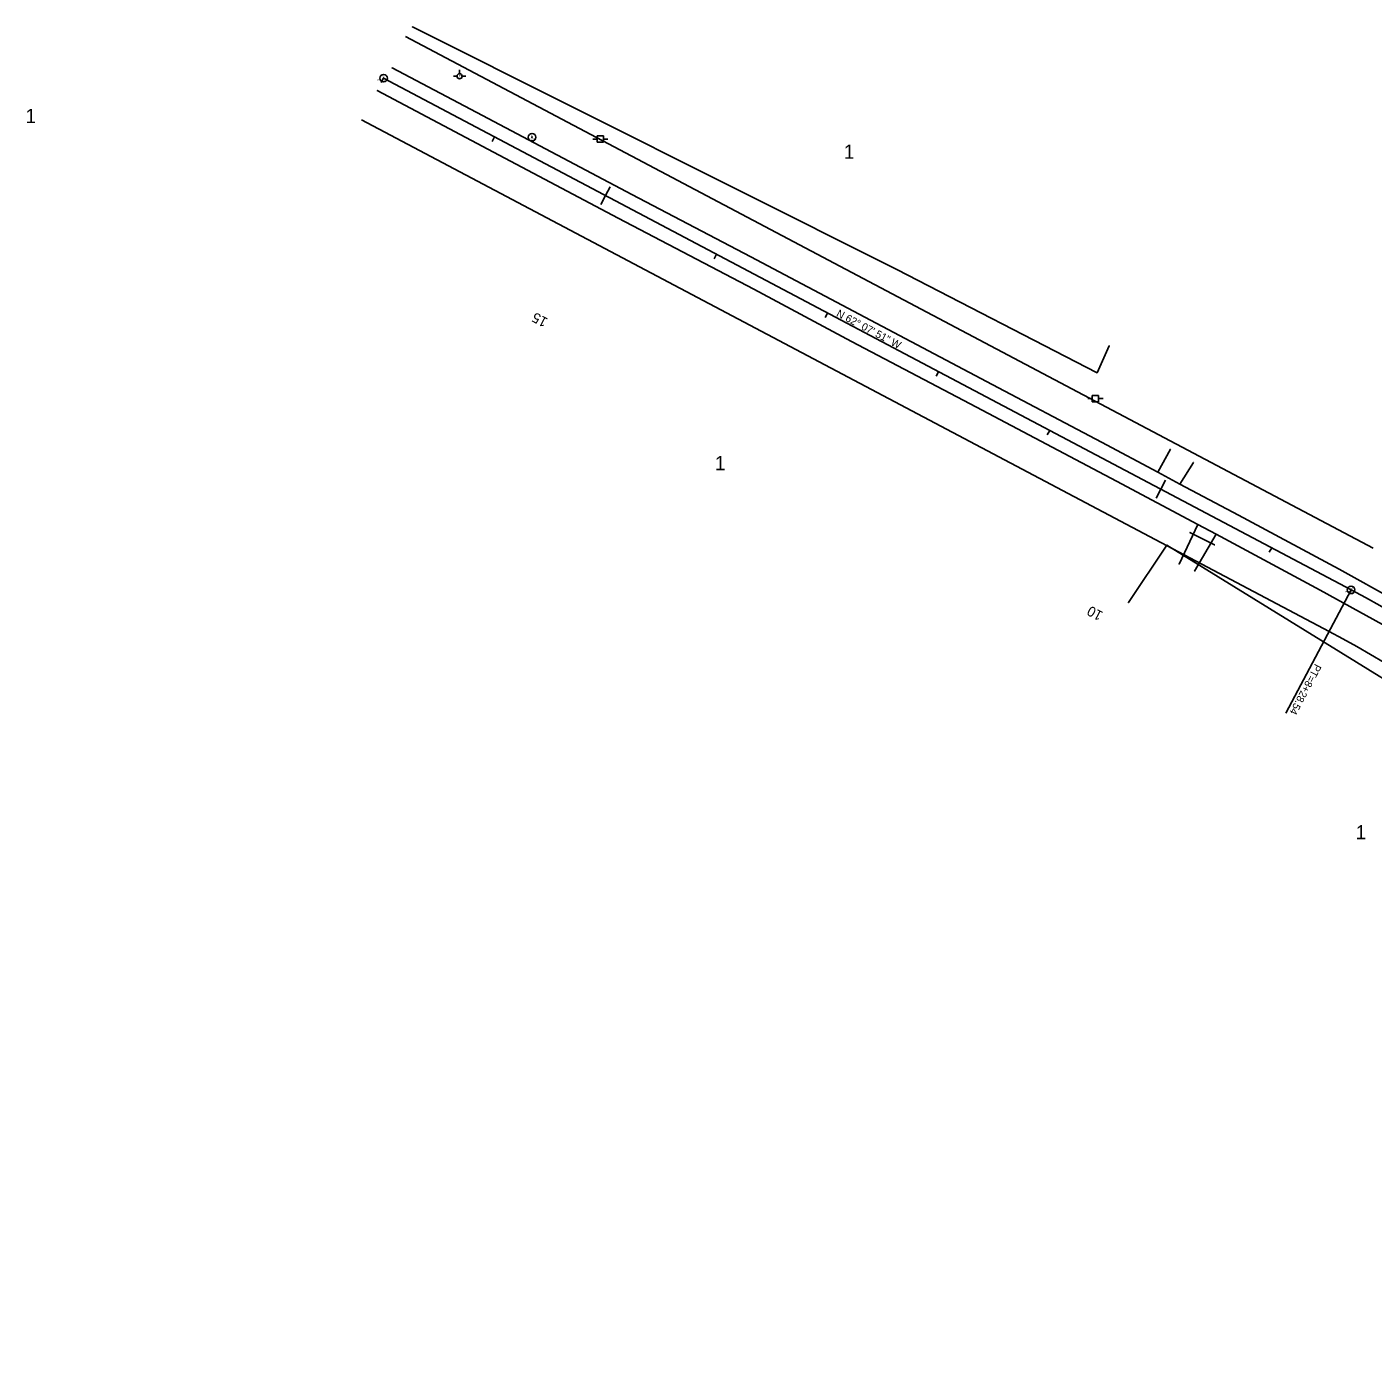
# Model space of a CAD drawing. Extents: x 2519952 to 2531965, y 848341 to 887632.
# Drawn here: x 2523997 to 2525069, y 851302 to 852373 of the extents above; entities that cross this region are included whole.
import ezdxf

# ---------------------------------------------------------------- set-up
doc = ezdxf.new("R2010")
doc.units = 0
for name, color, linetype in [('RD_EX_DR_Pipe', 7, 'Continuous'), ('RD_EX_Driveway', 7, 'Continuous'), ('RD_EX_DV_Prop', 7, 'Continuous'), ('RD_EX_DV_TX_Prop', 7, 'Continuous'), ('RD_EX_Road', 7, 'Continuous'), ('RD_EX_RW', 7, 'Continuous'), ('RD_EX_UT', 7, 'Continuous'), ('RD_EX_VEG', 7, 'Continuous'), ('RD_HC_Cl', 7, 'Continuous'), ('RD_HC_Data', 7, 'Continuous'), ('RD_HC_Data_Tic', 7, 'Continuous'), ('RD_HC_Survey_txCode', 7, 'Continuous'), ('RD_HC_TX_Sta50', 7, 'Continuous'), ('RD_HC_txCode', 7, 'Continuous'), ('RD_SMD_Locator', 7, 'Continuous')]:
    doc.layers.add(name, color=color, linetype=linetype)

msp = doc.modelspace()

# ---------------------------------------------------------------- linework, layer by layer
at = {"layer": 'RD_EX_DR_Pipe'}
msp.add_line((2524942.6, 851961), (2524923, 851971), dxfattribs=at)
at = {"layer": 'RD_EX_Driveway'}
for p, q in [((2524907.4, 852037.2), (2524897.5, 852018.9)), ((2524915, 852009.4), (2524925.7, 852026.7)), ((2524929.4, 851977.2), (2524914.4, 851945.7)), ((2524944, 851969.5), (2524926.7, 851940.1))]:
    msp.add_line(p, q, dxfattribs=at)
at = {"layer": 'RD_EX_DV_Prop'}
for p, q in [((2525068.8, 851958.4), (2524298.4, 852365.7)), ((2525033.8, 851892.1), (2524263.4, 852299.4))]:
    msp.add_line(p, q, dxfattribs=at)
msp.add_arc((2524604.9, 851081.1), 917.4, 12.4185, 62.1307, dxfattribs=at)
at = {"layer": 'RD_EX_Road'}
for points in [[(2525433.8, 851575), (2525391.3, 851640.7), (2525345.8, 851700), (2525314.8, 851735.8), (2525281.5, 851769.9), (2525254.2, 851795.5), (2525180.2, 851855.6), (2525143.2, 851881.7), (2525086.7, 851916.7), (2525041.8, 851941.8), (2524961.7, 851984.7), (2524915, 852009.4), (2524897.5, 852018.9), (2524852.7, 852042.7), (2524761, 852091.1), (2524664, 852142.2), (2524573.2, 852190.4), (2524478.7, 852239.9), (2524359.7, 852302.8), (2524287.6, 852340.8)], [(2525514.8, 851335.2), (2525495.5, 851394), (2525467.7, 851464.1), (2525437.7, 851524.6), (2525432.1, 851534.6), (2525373.4, 851627.9), (2525329.1, 851685.6), (2525298.4, 851721.2), (2525257.4, 851762.7), (2525212.7, 851802.4), (2525164.4, 851840), (2525123.3, 851868.7), (2525076.3, 851897.5), (2525026.6, 851925), (2524944, 851969.5), (2524929.4, 851977.2), (2524864.5, 852011.7), (2524753.1, 852070.7), (2524653.6, 852123), (2524575.7, 852164.6), (2524467.8, 852221.2), (2524372.9, 852271.3), (2524275.9, 852322.8)]]:
    msp.add_lwpolyline(points, dxfattribs=at)
at = {"layer": 'RD_EX_RW'}
for p, q in [((2525068.8, 851958.4), (2524298.4, 852365.7)), ((2525068.8, 851958.4), (2524298.4, 852365.7)), ((2525033.8, 851892.1), (2524263.4, 852299.4))]:
    msp.add_line(p, q, dxfattribs=at)
msp.add_arc((2524604.9, 851081.1), 917.4, 12.4185, 62.1308, dxfattribs=at)
at = {"layer": 'RD_EX_UT'}
for p, q in [((2524336.5, 852334.1), (2524339.4, 852334.1)), ((2524341.4, 852339.2), (2524341.4, 852336.1)), ((2524343.4, 852334.1), (2524346.5, 852334.1)), ((2524447.5, 852284.1), (2524451, 852284.1)), ((2524455.9, 852286.7), (2524450.9, 852286.7)), ((2524450.9, 852286.7), (2524450.9, 852281.7)), ((2524450.9, 852281.7), (2524455.9, 852281.7)), ((2524455.9, 852281.7), (2524455.9, 852286.7)), ((2524455.9, 852284.1), (2524459.5, 852284.1)), ((2524841.8, 852077.5), (2524845.3, 852077.5)), ((2524850.2, 852080), (2524845.2, 852080)), ((2524845.2, 852080), (2524845.2, 852075)), ((2524845.2, 852075), (2524850.2, 852075)), ((2524850.2, 852075), (2524850.2, 852080)), ((2524850.2, 852077.5), (2524853.8, 852077.5))]:
    msp.add_line(p, q, dxfattribs=at)
msp.add_circle((2524341.4, 852334.1), 2, dxfattribs=at)
at = {"layer": 'RD_EX_VEG'}
for points in [[(2524858.7, 852119.6), (2524849.1, 852098), (2524689.7, 852180.3), (2524303.8, 852373.4)], [(2525469.7, 851393.8), (2525414.8, 851521.3), (2525323.7, 851670), (2525307.9, 851664.1), (2525134.7, 851818.8), (2525055.6, 851867.6), (2524904.6, 851960.9), (2524874, 851915.1)]]:
    msp.add_lwpolyline(points, dxfattribs=at)
at = {"layer": 'RD_HC_Cl'}
msp.add_line((2525051.3, 851925.2), (2524280.9, 852332.6), dxfattribs=at)
msp.add_arc((2524604.9, 851081.1), 954.9, 12.4185, 62.1308, dxfattribs=at)
at = {"layer": 'RD_HC_Data'}
msp.add_line((2525051.3, 851925.2), (2524999.3, 851826.9), dxfattribs=at)
for centre, radius in [((2524280.9, 852332.6), 3), ((2524280.9, 852332.6), 0.282), ((2524399.1, 852285.6), 3), ((2524399.1, 852285.6), 0.282), ((2525051.3, 851925.2), 3), ((2525051.3, 851925.2), 0.282)]:
    msp.add_circle(centre, radius, dxfattribs=at)
at = {"layer": 'RD_HC_Data_Tic'}
for p, q in [((2524280.9, 852332.6), (2524279, 852329.1)), ((2524369.3, 852285.9), (2524367.4, 852282.3)), ((2524457.7, 852239.1), (2524461.4, 852246.2)), ((2524457.7, 852239.1), (2524454, 852232)), ((2524546.1, 852192.4), (2524544.2, 852188.8)), ((2524634.5, 852145.6), (2524632.6, 852142.1)), ((2524722.9, 852098.9), (2524721, 852095.3)), ((2524811.3, 852052.1), (2524809.4, 852048.6)), ((2524899.7, 852005.4), (2524903.5, 852012.5)), ((2524899.7, 852005.4), (2524896, 851998.3)), ((2524988.1, 851958.6), (2524986.2, 851955.1))]:
    msp.add_line(p, q, dxfattribs=at)
at = {"layer": 'RD_SMD_Locator'}
for centre in [(2524303.8, 852373.4), (2524287.6, 852340.8), (2524280.9, 852332.6), (2524275.9, 852322.8), (2524359.7, 852302.8), (2524399.1, 852285.6), (2524372.9, 852271.3), (2524478.7, 852239.9), (2524467.8, 852221.2), (2524573.2, 852190.4), (2524689.7, 852180.3), (2524575.7, 852164.6), (2524664, 852142.2), (2524653.6, 852123), (2524858.7, 852119.6), (2524849.1, 852098), (2524761, 852091.1), (2524753.1, 852070.7), (2524852.7, 852042.7), (2524907.4, 852037.2), (2524925.7, 852026.7), (2524864.5, 852011.7), (2524897.5, 852018.9), (2524897.5, 852018.9), (2524915, 852009.4), (2524915, 852009.4), (2524929.4, 851977.2), (2524929.4, 851977.2), (2524961.7, 851984.7), (2524923, 851971), (2524944, 851969.5), (2524944, 851969.5), (2524904.6, 851960.9), (2524942.6, 851961), (2524914.4, 851945.7), (2524926.7, 851940.1), (2525041.8, 851941.8), (2525026.6, 851925), (2525051.3, 851925.2), (2524874, 851915.1), (2525055.6, 851867.6)]:
    msp.add_circle(centre, 0.001, dxfattribs=at)

# ---------------------------------------------------------------- texts
at = {"layer": 'RD_EX_DV_TX_Prop'}
for p in [(2523995.7, 852296.8), (2524647.4, 852268.4), (2524544.7, 852020.5), (2525055, 851726.6)]:
    msp.add_text('1', height=11.3, dxfattribs=at).set_placement(p)
at = {"layer": 'RD_EX_UT'}
msp.add_text('T', height=2, dxfattribs=at).set_placement((2524340.8, 852333.1))
at = {"layer": 'RD_HC_Data'}
msp.add_text('PT=8+28.54', height=6, rotation=242.1308, dxfattribs=at).set_placement((2525022.7, 851866.8))
at = {"layer": 'RD_HC_Survey_txCode'}
msp.add_text('N 62%%d 07\' 51" W', height=6, rotation=332.1308, dxfattribs=at).set_placement((2524640.9, 852143.4))
at = {"layer": 'RD_HC_TX_Sta50'}
for s, p in [('15', (2524412.3, 852140.9)), ('10', (2524854.4, 851907.2))]:
    msp.add_text(s, height=8, rotation=152.1308, dxfattribs=at).set_placement(p)
at = {"layer": 'RD_HC_txCode'}
for s, p in [('POT 17+00.00', (2524275.8, 852330.6)), ('20', (2524280.1, 852333.6)), ('8', (2524398.8, 852286.6)), ('CP 8 MSC', (2524395.5, 852283.6)), ('PT 8+28.54', (2525047, 851923.2)), ('18', (2525050.8, 851926.2))]:
    msp.add_text(s, height=1, dxfattribs=at).set_placement(p)

doc.saveas('drawing.dxf')
